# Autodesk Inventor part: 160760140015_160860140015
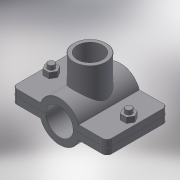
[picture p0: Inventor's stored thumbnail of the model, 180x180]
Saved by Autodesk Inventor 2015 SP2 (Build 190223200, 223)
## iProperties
Created: 2017-05
Part Number: 160760140015_160860140015
Material: Generic
Description: PLASSON SADDLE 140-1.1/2"
Document SubType Name: Modeling
Designer: KIM
Density: 1 g/cm^3
Appearance: Default
Author: KIM
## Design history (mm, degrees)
derived "16076.ipt"
feature "Solid1::16076.ipt"
feature "Solid2::16076.ipt"
tag "TaggingFeature1"
body "Solid1"
other parameters: "d0" = 154, "d1" = 201, "d4" = 136, "d5" = 0, "d6" = 10.05, "d7" = 201, "d8" = 0.1, "d10" = 0, "d11" = 1.4, "d14" = 58.2985, "d20" = 1.4, "d23" = 1.4, "d36" = 15, "d37" = 12, "d38" = 78, "d39" = 0, "d40" = 3, "d41" = 5, "d42" = 0, "d44" = 3, "d45" = 0, "d46" = 1.4, "d51" = 107, "d52" = 44.845, "d53" = 25, "d54" = 0, "d57" = 0, "d58" = 151.2, "d60" = 0, "d62" = 15, "d63" = 12, "d66" = 112, "G_" = 44.845, "A_" = 107, "L_" = 201, "L_1" = 136, "l_2" = 25
